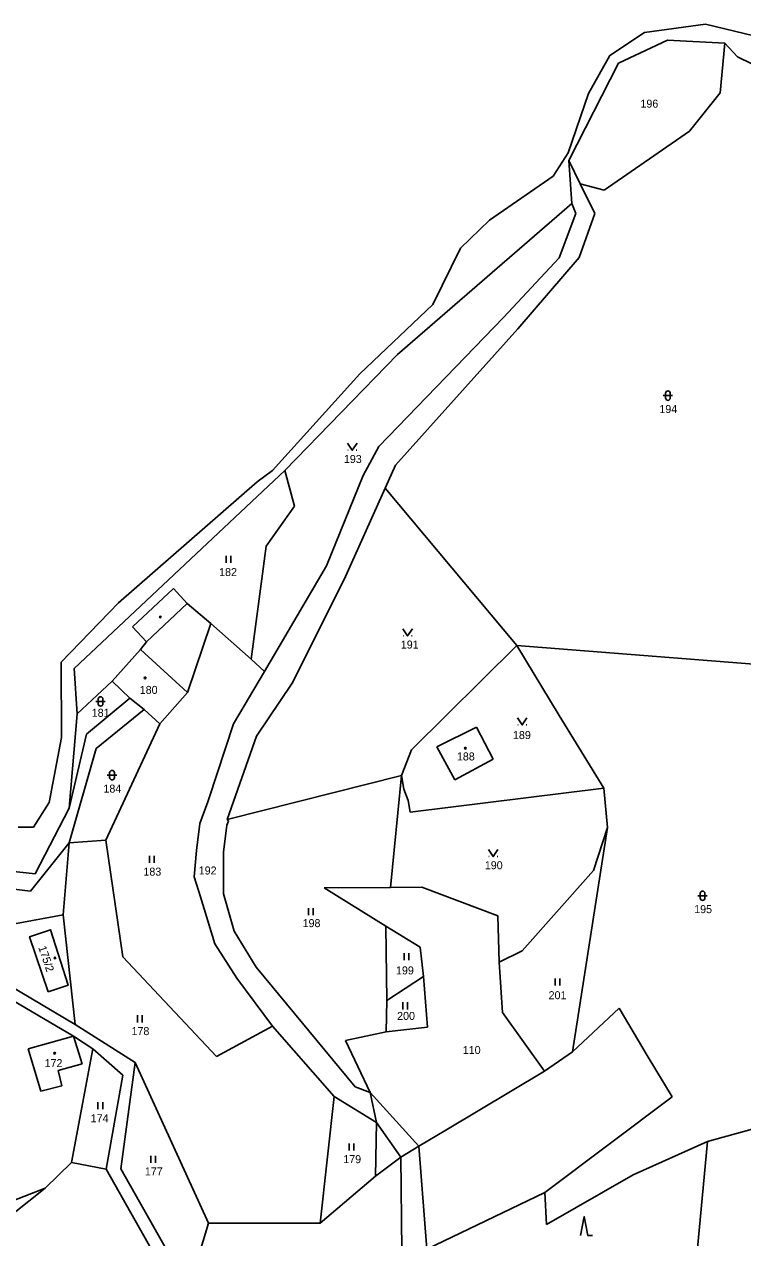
# Model space of a CAD drawing. Extents: x -670359 to -668019, y -978807 to -976674.
# Drawn here: x -669891.1 to -669738.5, y -977216.7 to -976959 of the extents above; entities that cross this region are included whole.
import ezdxf

# ---------------------------------------------------------------- set-up
doc = ezdxf.new("R2010")
doc.units = 0
for name, color, linetype in [('Hranice kat_území', 7, 'Continuous'), ('Hranice parcel', 7, 'Continuous'), ('Parcelní čísla', 7, 'Continuous'), ('Vnitřní kresba', 7, 'Continuous'), ('Značky budov', 7, 'Continuous'), ('Značky kultur', 7, 'Continuous')]:
    doc.layers.add(name, color=color, linetype=linetype)

msp = doc.modelspace()

# ---------------------------------------------------------------- linework, layer by layer
at = {"layer": 'Hranice kat_území'}
for points in [[(-669759.32, -976960.73), (-669746.37, -976958.97)], [(-669746.37, -976958.97), (-669732.04, -976962.4)], [(-669766.7, -976965.6), (-669759.32, -976960.73)], [(-669771.24, -976973.67), (-669766.7, -976965.6)], [(-669775.57, -976986.24), (-669771.24, -976973.67)], [(-669778.75, -976991.21), (-669775.57, -976986.24)], [(-669792.29, -977000.56), (-669778.75, -976991.21)], [(-669798.42, -977006.51), (-669792.29, -977000.56)], [(-669804.3, -977018.5), (-669798.42, -977006.51)], [(-669819.79, -977033.2), (-669804.3, -977018.5)], [(-669838.37, -977053.76), (-669819.79, -977033.2)], [(-669841.61, -977056.14), (-669838.37, -977053.76)], [(-669871.1, -977081.85), (-669841.61, -977056.14)], [(-669883.27, -977094.43), (-669871.1, -977081.85)], [(-669883.18, -977110.42), (-669883.27, -977094.43)], [(-669885.83, -977124.27), (-669883.18, -977110.42)], [(-669889.16, -977129.48), (-669885.83, -977124.27)], [(-669892.44, -977129.5), (-669889.16, -977129.48)]]:
    msp.add_lwpolyline(points, dxfattribs=at)
at = {"layer": 'Hranice parcel'}
for points in [[(-669754.48, -976962.35), (-669764.9, -976967.23)], [(-669742.25, -976963), (-669754.48, -976962.35)], [(-669742.25, -976963), (-669743.27, -976973.56)], [(-669739.62, -976965.89), (-669742.25, -976963)], [(-669764.9, -976967.23), (-669775.41, -976987.93)], [(-669727.11, -976971.96), (-669739.62, -976965.89)], [(-669743.27, -976973.56), (-669749.78, -976981.69)], [(-669749.78, -976981.69), (-669767.93, -976994.21)], [(-669775.41, -976987.93), (-669774.8, -976997.02)], [(-669773.04, -976992.88), (-669775.41, -976987.93)], [(-669767.93, -976994.21), (-669773.04, -976992.88)], [(-669769.91, -976999.15), (-669773.04, -976992.88)], [(-669774.8, -976997.02), (-669811.81, -977029.13)], [(-669774.8, -976997.02), (-669773.91, -976999.17)], [(-669773.91, -976999.17), (-669777.45, -977008.54)], [(-669773.22, -977008.52), (-669769.91, -976999.15)], [(-669777.45, -977008.54), (-669789.3, -977021.24)], [(-669786.25, -977023.62), (-669773.22, -977008.52)], [(-669789.3, -977021.24), (-669815.78, -977048.65)], [(-669812.24, -977052.62), (-669786.25, -977023.62)], [(-669811.81, -977029.13), (-669835.75, -977053.72)], [(-669815.78, -977048.65), (-669819.11, -977054.82)], [(-669814.46, -977057.51), (-669812.24, -977052.62)], [(-669835.75, -977053.72), (-669880.54, -977095.78)], [(-669835.75, -977053.72), (-669833.71, -977061.3)], [(-669819.11, -977054.82), (-669826.92, -977073.97)], [(-669823.15, -977076.9), (-669814.46, -977057.51)], [(-669786.45, -977090.91), (-669814.46, -977057.51)], [(-669833.71, -977061.3), (-669839.74, -977069.81)], [(-669839.74, -977069.81), (-669842.89, -977093.8)], [(-669826.92, -977073.97), (-669840.08, -977096.42)], [(-669834.22, -977098.94), (-669823.15, -977076.9)], [(-669868.12, -977086.92), (-669859.44, -977078.8)], [(-669859.44, -977078.8), (-669856.47, -977081.98)], [(-669856.47, -977081.98), (-669851.49, -977086.26)], [(-669856.45, -977100.92), (-669851.49, -977086.26)], [(-669851.49, -977086.26), (-669842.89, -977093.8)], [(-669865.14, -977090.1), (-669868.12, -977086.92)], [(-669866.41, -977091.78), (-669865.14, -977090.1)], [(-669786.45, -977090.91), (-669808.88, -977113.1)], [(-669729.8, -977095.37), (-669786.45, -977090.91)], [(-669777.5, -977105.81), (-669786.45, -977090.91)], [(-669872.45, -977098.45), (-669866.41, -977091.78)], [(-669842.89, -977093.8), (-669840.08, -977096.42)], [(-669880.54, -977095.78), (-669879.85, -977105.45)], [(-669840.08, -977096.42), (-669846.65, -977107.57)], [(-669879.85, -977105.45), (-669872.45, -977098.45)], [(-669872.45, -977098.45), (-669868.67, -977102.11)], [(-669841.76, -977110.18), (-669834.22, -977098.94)], [(-669862.33, -977107.58), (-669856.45, -977100.92)], [(-669877.91, -977109.75), (-669868.67, -977102.11)], [(-669868.67, -977102.11), (-669865.62, -977104.49)], [(-669879.85, -977105.45), (-669881.58, -977125.44)], [(-669865.62, -977104.49), (-669875.81, -977112.78)], [(-669865.62, -977104.49), (-669862.33, -977107.58)], [(-669768, -977121.2), (-669777.5, -977105.81)], [(-669873.79, -977132.26), (-669862.33, -977107.58)], [(-669846.65, -977107.57), (-669851.93, -977123.5)], [(-669803.44, -977112.43), (-669795.07, -977108.22)], [(-669795.07, -977108.22), (-669791.51, -977115.07)], [(-669881.58, -977125.44), (-669877.91, -977109.75)], [(-669847.98, -977127.88), (-669841.76, -977110.18)], [(-669875.81, -977112.78), (-669881.54, -977132.79)], [(-669808.88, -977113.1), (-669811, -977118.5)], [(-669799.65, -977119.44), (-669803.44, -977112.43)], [(-669791.51, -977115.07), (-669799.65, -977119.44)], [(-669811, -977118.5), (-669847.98, -977127.88)], [(-669813.28, -977142.29), (-669811, -977118.5)], [(-669810.44, -977121.39), (-669811, -977118.5)], [(-669809.57, -977123.81), (-669810.44, -977121.39)], [(-669768, -977121.2), (-669809.11, -977126.3)], [(-669767.2, -977129.55), (-669768, -977121.2)], [(-669852.08, -977124.14), (-669853.82, -977128.71)], [(-669851.93, -977123.5), (-669852.08, -977124.14)], [(-669809.11, -977126.3), (-669809.57, -977123.81)], [(-669881.58, -977125.44), (-669888.79, -977139.39)], [(-669853.82, -977128.71), (-669854.5, -977134.47)], [(-669848.06, -977129.07), (-669848.75, -977134.83)], [(-669847.74, -977128.19), (-669848.06, -977129.07)], [(-669847.98, -977127.88), (-669847.74, -977128.19)], [(-669774.62, -977177.22), (-669767.2, -977129.55)], [(-669767.2, -977129.55), (-669770.19, -977138.68)], [(-669881.54, -977132.79), (-669873.79, -977132.26)], [(-669873.79, -977132.26), (-669870.14, -977157.02)], [(-669881.54, -977132.79), (-669889.81, -977143.07)], [(-669881.54, -977132.79), (-669882.82, -977148.14)], [(-669854.5, -977134.47), (-669855.03, -977140.06)], [(-669848.75, -977134.83), (-669848.78, -977143.62)], [(-669888.79, -977139.39), (-669894.63, -977138.78)], [(-669855.03, -977140.06), (-669853.65, -977144.29)], [(-669770.19, -977138.68), (-669785.3, -977155.79)], [(-669889.81, -977143.07), (-669908.05, -977140.86)], [(-669813.28, -977142.29), (-669827.43, -977142.38)], [(-669827.43, -977142.38), (-669814.27, -977150.53)], [(-669806.64, -977142.25), (-669813.28, -977142.29)], [(-669790.53, -977148.31), (-669806.64, -977142.25)], [(-669853.65, -977144.29), (-669850.64, -977154.26)], [(-669848.78, -977143.62), (-669846.5, -977151.6)], [(-669882.82, -977148.14), (-669880.3, -977171.38)], [(-669814.27, -977150.53), (-669814.11, -977166.27)], [(-669806.97, -977154.96), (-669814.27, -977150.53)], [(-669790.24, -977158.14), (-669790.53, -977148.31)], [(-669910.86, -977153.26), (-669880.3, -977171.38)], [(-669886.03, -977164.48), (-669889.97, -977152.78), (-669885.57, -977151.29), (-669881.81, -977163.06), (-669886.03, -977164.48)], [(-669846.5, -977151.6), (-669841.82, -977159.24)], [(-669912.21, -977155.35), (-669880.68, -977173.86)], [(-669850.64, -977154.26), (-669845.96, -977161.59)], [(-669806.3, -977161.19), (-669806.97, -977154.96)], [(-669785.3, -977155.79), (-669790.24, -977158.14)], [(-669870.14, -977157.02), (-669850.27, -977178.23)], [(-669790.24, -977158.14), (-669789.54, -977168.84)], [(-669841.82, -977159.24), (-669820.81, -977184.61)], [(-669845.96, -977161.59), (-669838.39, -977171.77)], [(-669806.3, -977161.19), (-669814.11, -977166.27)], [(-669805.44, -977171.97), (-669806.3, -977161.19)], [(-669814.11, -977166.27), (-669814.23, -977172.98)], [(-669764.74, -977167.95), (-669774.62, -977177.22)], [(-669758.79, -977177.95), (-669764.74, -977167.95)], [(-669789.54, -977168.84), (-669780.6, -977181.33)], [(-669880.68, -977173.86), (-669890.26, -977176.55)], [(-669878.81, -977179.76), (-669880.68, -977173.86)], [(-669880.68, -977173.86), (-669876.51, -977176.55)], [(-669880.3, -977171.38), (-669867.54, -977179.46)], [(-669850.27, -977178.23), (-669838.39, -977171.77)], [(-669838.39, -977171.77), (-669825.27, -977186.72)], [(-669814.23, -977172.98), (-669822.86, -977174.79)], [(-669814.23, -977172.98), (-669805.44, -977171.97)], [(-669822.86, -977174.79), (-669817.6, -977185.87)], [(-669890.26, -977176.55), (-669887.58, -977185.57)], [(-669876.51, -977176.55), (-669881.1, -977200.71)], [(-669876.51, -977176.55), (-669870.16, -977182.19)], [(-669780.6, -977181.33), (-669774.62, -977177.22)], [(-669753.49, -977186.78), (-669758.79, -977177.95)], [(-669883.92, -977181.15), (-669878.81, -977179.76)], [(-669883.1, -977184.42), (-669883.92, -977181.15)], [(-669870.61, -977202.09), (-669867.54, -977179.46)], [(-669867.54, -977179.46), (-669852, -977213.57)], [(-669870.16, -977182.19), (-669873.73, -977202.11)], [(-669887.58, -977185.57), (-669883.1, -977184.42)], [(-669825.27, -977186.72), (-669828.26, -977213.6)], [(-669825.27, -977186.72), (-669816.29, -977192.18)], [(-669820.81, -977184.61), (-669817.6, -977185.87)], [(-669817.6, -977185.87), (-669816.29, -977192.18)], [(-669780.54, -977207.07), (-669753.49, -977186.78)], [(-669720.82, -977189.29), (-669745.97, -977196.23)], [(-669816.29, -977192.18), (-669816.49, -977203.63)], [(-669745.97, -977196.23), (-669761.77, -977203.36)], [(-669745.97, -977196.23), (-669748.39, -977221.98)], [(-669886.67, -977206.18), (-669881.1, -977200.71)], [(-669881.1, -977200.71), (-669873.73, -977202.11)], [(-669873.73, -977202.11), (-669861.38, -977223.93)], [(-669859.63, -977221.44), (-669870.61, -977202.09)], [(-669816.49, -977203.63), (-669828.26, -977213.6)], [(-669761.77, -977203.36), (-669780.18, -977213.86)], [(-669901.59, -977211.94), (-669886.67, -977206.18)], [(-669886.67, -977206.18), (-669893.28, -977211.41)], [(-669780.54, -977207.07), (-669805.6, -977219.15)], [(-669780.18, -977213.86), (-669780.54, -977207.07)], [(-669852, -977213.57), (-669855.6, -977225.55)], [(-669828.26, -977213.6), (-669852, -977213.57)]]:
    msp.add_lwpolyline(points, dxfattribs=at)
at = {"layer": 'Vnitřní kresba'}
for points in [[(-669865.14, -977090.1), (-669856.47, -977081.98)], [(-669866.41, -977091.78), (-669856.45, -977100.92)], [(-669910.86, -977153.26), (-669882.82, -977148.14)], [(-669801.56, -977193.85), (-669780.6, -977181.33)], [(-669817.6, -977185.87), (-669807.3, -977197.24)], [(-669816.29, -977192.18), (-669811.13, -977199.58)], [(-669801.56, -977193.85), (-669807.3, -977197.24)], [(-669816.49, -977203.63), (-669811.13, -977199.58)], [(-669811.13, -977199.58), (-669807.3, -977197.24)], [(-669811.13, -977199.58), (-669810.87, -977219.4)], [(-669807.3, -977197.24), (-669805.6, -977219.15)]]:
    msp.add_lwpolyline(points, dxfattribs=at)
at = {"layer": 'Značky budov'}
for centre in [(-669865.44, -977097.78), (-669797.41, -977112.72), (-669884.58, -977157.26), (-669884.65, -977177.5)]:
    msp.add_circle(centre, 0.175, dxfattribs=at)
at = {"layer": 'Značky kultur'}
for p, q in [((-669755.37, -977037.84), (-669753.37, -977037.84)), ((-669754.87, -977037.34), (-669754.87, -977038.34)), ((-669753.87, -977037.34), (-669753.87, -977038.34)), ((-669822.37, -977049.45), (-669822.27, -977049.45)), ((-669820.57, -977049.45), (-669820.47, -977049.45)), ((-669848.21, -977071.86), (-669848.21, -977073.36)), ((-669847.21, -977073.36), (-669847.21, -977071.86)), ((-669810.61, -977088.86), (-669810.51, -977088.86)), ((-669808.81, -977088.86), (-669808.71, -977088.86)), ((-669875.89, -977102.78), (-669873.89, -977102.78)), ((-669875.39, -977102.28), (-669875.39, -977103.28)), ((-669874.39, -977102.28), (-669874.39, -977103.28)), ((-669786.27, -977107.76), (-669786.17, -977107.76)), ((-669784.47, -977107.76), (-669784.37, -977107.76)), ((-669873.47, -977118.45), (-669871.47, -977118.45)), ((-669872.97, -977117.95), (-669872.97, -977118.95)), ((-669871.97, -977117.95), (-669871.97, -977118.95)), ((-669864.51, -977135.58), (-669864.51, -977137.08)), ((-669863.51, -977137.08), (-669863.51, -977135.58)), ((-669792.43, -977135.73), (-669792.33, -977135.73)), ((-669790.63, -977135.73), (-669790.53, -977135.73)), ((-669748, -977144.05), (-669746, -977144.05)), ((-669747.5, -977143.55), (-669747.5, -977144.55)), ((-669746.5, -977143.55), (-669746.5, -977144.55)), ((-669830.72, -977146.67), (-669830.72, -977148.17)), ((-669829.72, -977148.17), (-669829.72, -977146.67)), ((-669810.38, -977156.25), (-669810.38, -977157.75)), ((-669809.38, -977157.75), (-669809.38, -977156.25)), ((-669778.31, -977161.63), (-669778.31, -977163.13)), ((-669777.31, -977163.13), (-669777.31, -977161.63)), ((-669810.7, -977166.69), (-669810.7, -977168.19)), ((-669809.7, -977168.19), (-669809.7, -977166.69)), ((-669867.04, -977169.45), (-669867.04, -977170.95)), ((-669866.04, -977170.95), (-669866.04, -977169.45)), ((-669875.45, -977187.88), (-669875.45, -977189.38)), ((-669874.45, -977189.38), (-669874.45, -977187.88)), ((-669822.09, -977196.65), (-669822.09, -977198.15)), ((-669821.09, -977198.15), (-669821.09, -977196.65)), ((-669864.2, -977199.26), (-669864.2, -977200.76)), ((-669863.2, -977200.76), (-669863.2, -977199.26))]:
    msp.add_line(p, q, dxfattribs=at)
for points in [[(-669822.42, -977047.95), (-669821.42, -977049.45), (-669820.42, -977047.95)], [(-669810.66, -977087.36), (-669809.66, -977088.86), (-669808.66, -977087.36)], [(-669786.32, -977106.26), (-669785.32, -977107.76), (-669784.32, -977106.26)], [(-669792.48, -977134.23), (-669791.48, -977135.73), (-669790.48, -977134.23)], [(-669772.91, -977216.2), (-669772.16, -977212.2), (-669771.41, -977216.2), (-669770.41, -977216.2)]]:
    msp.add_lwpolyline(points, dxfattribs=at)
for centre in [(-669862.19, -977084.87), (-669865.44, -977097.78), (-669797.41, -977112.72), (-669884.58, -977157.26), (-669884.65, -977177.5)]:
    msp.add_circle(centre, 0.175, dxfattribs=at)
for centre, start, end in [((-669754.37, -977037.34), 0, 180), ((-669754.37, -977038.34), 180, 0), ((-669874.89, -977102.28), 0, 180), ((-669874.89, -977103.28), 180, 0), ((-669872.47, -977117.95), 0, 180), ((-669872.47, -977118.95), 180, 0), ((-669747, -977143.55), 0, 180), ((-669747, -977144.55), 180, 0)]:
    msp.add_arc(centre, 0.5, start, end, dxfattribs=at)

# ---------------------------------------------------------------- texts
at = {"layer": 'Parcelní čísla'}
for s, p in [('196', (-669760.21, -976976.68)), ('194', (-669756.19, -977041.54)), ('193', (-669823.21, -977052.15)), ('182', (-669849.72, -977076.16)), ('191', (-669811.12, -977091.56)), ('180', (-669866.58, -977101.19)), ('181', (-669876.78, -977106.05)), ('189', (-669787.29, -977110.78)), ('188', (-669799.2, -977115.32)), ('184', (-669874.29, -977122.15)), ('192', (-669854.05, -977139.54)), ('190', (-669793.27, -977138.43)), ('183', (-669865.8, -977139.78)), ('195', (-669748.79, -977147.75)), ('198', (-669831.98, -977150.72)), ('199', (-669812.14, -977160.76)), ('201', (-669779.72, -977166.03)), ('200', (-669811.9, -977170.43)), ('178', (-669868.33, -977173.65)), ('110', (-669797.95, -977177.67)), ('172', (-669886.79, -977180.45)), ('174', (-669877, -977192.17)), ('179', (-669823.34, -977200.85)), ('177', (-669865.49, -977203.46))]:
    msp.add_text(s, height=1.7, dxfattribs=at).set_placement(p)
msp.add_text('175/2', height=1.7, rotation=288.7134, dxfattribs=at).set_placement((-669888.15, -977155.02))

doc.saveas('drawing.dxf')
